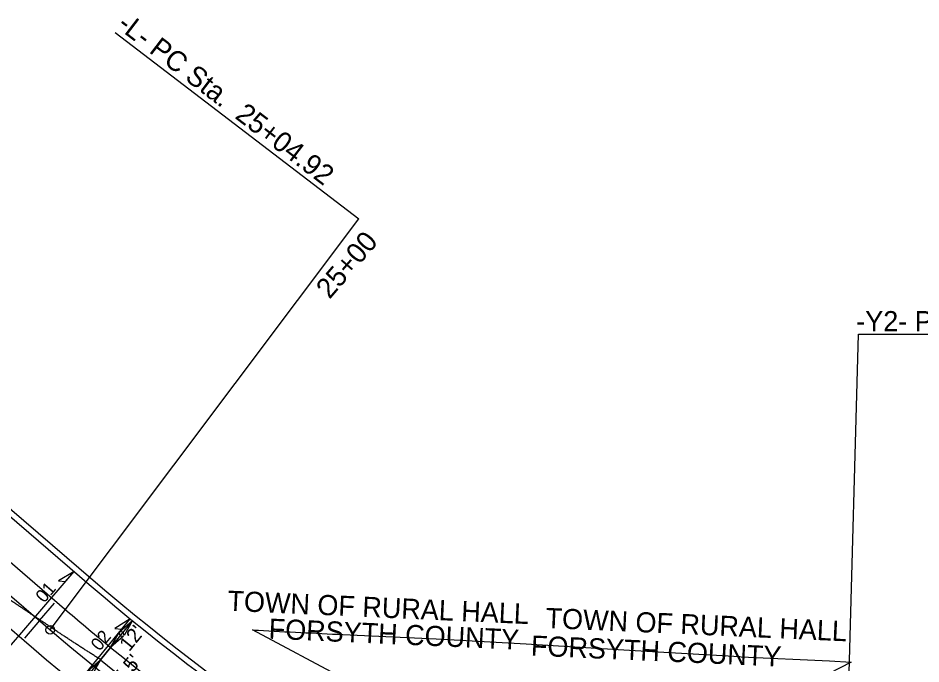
# Model space of a CAD drawing. Extents: x 1616561 to 1622460, y 896726 to 899651.
# Drawn here: x 1619267.2 to 1619580.2, y 898222.4 to 898446.5 of the extents above; entities that cross this region are included whole.
import ezdxf

# ---------------------------------------------------------------- set-up
doc = ezdxf.new("R2010")
doc.units = 0
for name, color, linetype in [('Old_Level_3', 7, 'Continuous'), ('Prop Dimension', 7, 'Continuous'), ('Prop DSN Text', 7, 'Continuous'), ('Prop Horizontal Alignment Tick Small', 7, 'Continuous'), ('Prop North Arrow NAD83 for Plan Sheets CELL', 7, 'Continuous'), ('Prop Rem of Exist Asph Pvmt', 7, 'Continuous'), ('Prop Superelevation Label', 7, 'Continuous'), ('Prop Terminator CELL', 7, 'Continuous'), ('Sheet Cutting Line CELL', 7, 'Continuous'), ('Sheet North Arrow CELL', 7, 'Continuous'), ('Sheet Sticker Preliminary CELL', 7, 'Continuous')]:
    doc.layers.add(name, color=color, linetype=linetype)

msp = doc.modelspace()

# ---------------------------------------------------------------- linework, layer by layer
at = {"layer": 'Old_Level_3'}
for p, q in [((1619233.52, 898284.32), (1619284.05, 898240.93)), ((1619222.12, 898271.04), (1619272.65, 898227.65)), ((1619295.8, 898223.93), (1619299.27, 898228.19)), ((1619299.27, 898228.19), (1619295.8, 898223.93)), ((1619295.8, 898223.92), (1619295.8, 898223.93))]:
    msp.add_line(p, q, dxfattribs=at)
for radius, start, end in [(791.25, 229.34838, 230.78618), (808.75, 229.34838, 255.58792), (791.25, 230.78618, 245.11013), (796.75, 230.7866, 245.11013)]:
    msp.add_arc((1619799.51, 898841.24), radius, start, end, dxfattribs=at)
msp.add_spline([(1619295.8, 898223.93), (1619294.65, 898224.65), (1619294.08, 898225.02), (1619293.51, 898225.38), (1619292.94, 898225.74), (1619292.36, 898226.11), (1619291.79, 898226.48), (1619291.22, 898226.84), (1619290.65, 898227.21), (1619290.08, 898227.58), (1619289.51, 898227.95), (1619288.94, 898228.31), (1619288.37, 898228.68), (1619287.8, 898229.05), (1619287.23, 898229.42), (1619286.67, 898229.79), (1619286.1, 898230.17), (1619285.53, 898230.54), (1619284.96, 898230.91), (1619284.39, 898231.28), (1619283.83, 898231.66), (1619283.26, 898232.03), (1619282.69, 898232.4), (1619282.13, 898232.78), (1619281.56, 898233.15), (1619280.99, 898233.53), (1619280.43, 898233.91), (1619279.86, 898234.28), (1619279.3, 898234.66), (1619278.73, 898235.04), (1619278.17, 898235.42), (1619277.6, 898235.8), (1619277.04, 898236.18), (1619276.47, 898236.55), (1619275.9, 898236.93), (1619275.34, 898237.31), (1619274.77, 898237.69), (1619274.21, 898238.07), (1619273.64, 898238.45), (1619273.08, 898238.83), (1619272.51, 898239.21), (1619271.95, 898239.58), (1619271.38, 898239.96), (1619270.82, 898240.34), (1619270.25, 898240.72), (1619269.68, 898241.1), (1619269.12, 898241.48), (1619268.55, 898241.86), (1619267.99, 898242.23), (1619267.42, 898242.61), (1619266.86, 898242.99), (1619266.29, 898243.37), (1619265.73, 898243.75), (1619265.16, 898244.13), (1619264.6, 898244.51), (1619264.03, 898244.89), (1619263.46, 898245.26), (1619262.9, 898245.64), (1619262.33, 898246.02), (1619261.77, 898246.4), (1619261.2, 898246.78), (1619260.64, 898247.16), (1619260.07, 898247.54), (1619259.51, 898247.91), (1619258.94, 898248.29), (1619258.38, 898248.67), (1619257.81, 898249.05), (1619257.25, 898249.43), (1619256.68, 898249.81), (1619256.11, 898250.19), (1619255.55, 898250.57), (1619254.98, 898250.94), (1619254.42, 898251.32), (1619253.85, 898251.7)], degree=3, dxfattribs=at)
at = {"layer": 'Prop Dimension'}
for p, q in [((1619306.86, 898237.48), (1619299.27, 898228.19)), ((1619295.8, 898223.93), (1619288.21, 898214.63))]:
    msp.add_line(p, q, dxfattribs=at)
at = {"layer": 'Prop Horizontal Alignment Tick Small'}
msp.add_line((1619242.64, 898294.94), (1619293.17, 898251.55), dxfattribs=at)
msp.add_arc((1619799.51, 898841.24), 777.25, 229.34838, 244.13867, dxfattribs=at)
at = {"layer": 'Prop North Arrow NAD83 for Plan Sheets CELL'}
for points in [[(1619286.61, 898254.55), (1619281.19, 898251.3), (1619283.6, 898251.04)], [(1619306.1, 898238.1), (1619300.76, 898234.72), (1619303.18, 898234.52)]]:
    msp.add_lwpolyline(points, close=True, dxfattribs=at)
at = {"layer": 'Prop Rem of Exist Asph Pvmt'}
for p, q in [((1619380.93, 898216.97), (1619348.44, 898234.23)), ((1619555.96, 898223.09), (1619538.96, 898214.39))]:
    msp.add_line(p, q, dxfattribs=at)
msp.add_lwpolyline([(1619379.82, 898232.66), (1619412.17, 898231.12), (1619443.36, 898229.43), (1619475.21, 898227.49), (1619491.02, 898226.59), (1619517.4, 898224.99), (1619517.84, 898224.97), (1619548.46, 898223.56), (1619555.96, 898223.09)], dxfattribs=at)
msp.add_spline([(1619348.44, 898234.23), (1619350.48, 898234.12), (1619379.82, 898232.66)], degree=3, dxfattribs=at)
at = {"layer": 'Prop Superelevation Label'}
for q in [(1619279.82, 898243.57), (1619269.4, 898231.43)]:
    msp.add_line((1619274.61, 898237.5), q, dxfattribs=at)
at = {"layer": 'Prop Terminator CELL'}
msp.add_line((1619241.34, 898293.42), (1619291.86, 898250.04), dxfattribs=at)
for points in [[(1619302.38, 898233.59), (1619306.86, 898237.48), (1619303.95, 898232.27), (1619303.61, 898233.51)], [(1619303.75, 898232.08), (1619299.27, 898228.19), (1619302.19, 898233.4), (1619302.52, 898232.16)], [(1619291.32, 898220.03), (1619295.8, 898223.93), (1619292.88, 898218.71), (1619292.55, 898219.95)]]:
    msp.add_lwpolyline(points, close=True, dxfattribs=at)
msp.add_arc((1619799.51, 898841.24), 779.25, 229.34838, 244.13867, dxfattribs=at)
at = {"layer": 'Sheet Cutting Line CELL'}
msp.add_line((1619227.82, 898277.68), (1619278.35, 898234.29), dxfattribs=at)
msp.add_arc((1619799.51, 898841.24), 800, 229.34838, 270, dxfattribs=at)
at = {"layer": 'Sheet North Arrow CELL'}
for p, q in [((1619300.83, 898441.53), (1619385.26, 898376.87)), ((1619278.35, 898234.29), (1619385.26, 898376.87)), ((1619553.58, 898157.53), (1619558.52, 898336.82)), ((1619558.52, 898336.82), (1619667.41, 898336.82))]:
    msp.add_line(p, q, dxfattribs=at)
msp.add_circle((1619278.35, 898234.29), 1.5, dxfattribs=at)
at = {"layer": 'Sheet Sticker Preliminary CELL'}
for p, q in [((1619259.58, 898223.06), (1619286.61, 898254.55)), ((1619279.83, 898205.98), (1619306.1, 898238.1))]:
    msp.add_line(p, q, dxfattribs=at)

# ---------------------------------------------------------------- texts
at = {"layer": 'Prop Dimension'}
for s, height, rotation, p in [('25+00', 7, 49.3484, (1619375.16, 898348.75)), ("12'", 5, 50.7862, (1619305.73, 898226.51)), ("5.5'", 5, 50.7862, (1619303.48, 898214.96))]:
    msp.add_text(s, height=height, rotation=rotation, dxfattribs=at).set_placement(p)
at = {"layer": 'Prop DSN Text'}
for s, p in [('TOWN OF RURAL HALL', (1619339.65, 898240.91)), ('TOWN OF RURAL HALL', (1619449.91, 898234.93)), ('FORSYTH COUNTY', (1619353.95, 898231.22)), ('FORSYTH COUNTY', (1619444.85, 898225.36))]:
    msp.add_text(s, height=7, rotation=357.4583, dxfattribs=at).set_placement(p)
at = {"layer": 'Sheet North Arrow CELL'}
for s, rotation, p in [('-L- PC Sta.  25+04.92', 322.554, (1619301.14, 898443.33)), ('-Y2- PC Sta.  10+73.40', 360, (1619557.73, 898337.86))]:
    msp.add_text(s, height=7, rotation=rotation, dxfattribs=at).set_placement(p)
at = {"layer": 'Sheet Sticker Preliminary CELL'}
for s, rotation, p in [('01', 49.3484, (1619276.23, 898243.36)), ('02', 50.5926, (1619295.45, 898226.65))]:
    msp.add_text(s, height=4.5, rotation=rotation, dxfattribs=at).set_placement(p)

doc.saveas('drawing.dxf')
